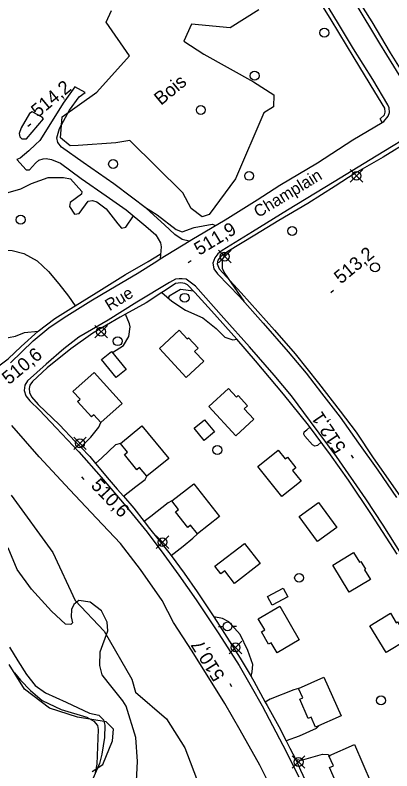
# Model space of a CAD drawing. Extents: x 347059 to 352153, y 6073752 to 6078601.
# Drawn here: x 348714.1 to 348840.8, y 6075207.5 to 6075461.9 of the extents above; entities that cross this region are included whole.
import ezdxf

# ---------------------------------------------------------------- set-up
doc = ezdxf.new("R2010")
doc.units = 0
for name, color, linetype in [('Level 1', 7, 'Continuous'), ('Level 19', 7, 'Continuous'), ('Level 2', 7, 'Continuous'), ('Level 21', 7, 'Continuous'), ('Level 22', 7, 'Continuous'), ('Level 3', 7, 'Continuous'), ('Level 31', 7, 'Continuous'), ('Level 36', 7, 'Continuous'), ('Level 4', 7, 'Continuous'), ('Level 44', 7, 'Continuous')]:
    doc.layers.add(name, color=color, linetype=linetype)

msp = doc.modelspace()

# ---------------------------------------------------------------- linework, layer by layer
at = {"layer": 'Level 1'}
msp.add_lwpolyline([(348754.72, 6075199.82), (348755.28, 6075210.65), (348754.72, 6075218.69), (348751.45, 6075229.25), (348750.34, 6075231.12), (348745.39, 6075237.26), (348743.4, 6075239.84), (348742.57, 6075242.92), (348742.68, 6075247.6), (348745.31, 6075254.6), (348745.04, 6075257.55), (348743.18, 6075261.42), (348739.33, 6075264.33), (348735.5, 6075264.86), (348733.89, 6075263.52), (348733.03, 6075261.83), (348732.92, 6075259.33), (348733.4, 6075257.32), (348732.85, 6075256.79), (348731.05, 6075256.88), (348726.3, 6075261.31), (348719.57, 6075268.69), (348714.74, 6075275.31), (348711.69, 6075282.58)], dxfattribs=at)
at = {"layer": 'Level 19'}
for points in [[(348772.58, 6075385.79), (348770.33, 6075386.41), (348767.77, 6075388.04), (348764.32, 6075391.28), (348758.33, 6075396.76), (348753.26, 6075400.67), (348747.29, 6075405.12), (348736.94, 6075412.32), (348729.69, 6075417.5), (348728.43, 6075419.01), (348728.13, 6075420.64), (348728.99, 6075423.76), (348732.4, 6075429.89), (348735.61, 6075434.35), (348737.68, 6075435.84), (348734.12, 6075437.77), (348730.24, 6075432.3), (348723.71, 6075421.79), (348722.41, 6075419.73), (348720.96, 6075418.31), (348718.68, 6075416.26), (348715.81, 6075413.74), (348714.61, 6075413.27), (348717.83, 6075409.78), (348718.97, 6075409.8), (348720.91, 6075412.08), (348722.03, 6075413.08), (348723.51, 6075413.56), (348724.55, 6075413.67), (348726.32, 6075413.26), (348729.38, 6075412.04), (348736.35, 6075406.92), (348744.73, 6075401.1), (348751.42, 6075396.41), (348758.11, 6075390.91), (348761.37, 6075387.9), (348763.02, 6075385.28), (348763.26, 6075383.9), (348762.93, 6075379.82)], [(348708.62, 6075382.07), (348710.74, 6075382.77), (348713.04, 6075382.72), (348717.06, 6075381.7), (348721.52, 6075379.23), (348725.3, 6075375.59), (348728.78, 6075371.41), (348732.03, 6075367.33), (348734.32, 6075364.05)], [(348763.41, 6075368.49), (348766.82, 6075365.67), (348771.39, 6075362.62), (348777.2, 6075359.99), (348781.68, 6075356.41), (348784.67, 6075353.54), (348787.3, 6075352.64), (348788.63, 6075352.77)], [(348746.8, 6075348.29), (348750.56, 6075350.66), (348752.32, 6075353.7), (348752.75, 6075356.98), (348752.55, 6075357.95), (348751.2, 6075361.22)], [(348701.43, 6075348.24), (348702.24, 6075350.79), (348702.71, 6075351.41), (348707.09, 6075352.48), (348714.22, 6075353.87), (348717.26, 6075355.11), (348721.81, 6075355.53)], [(348736.14, 6075316.5), (348739.54, 6075319.84), (348742.28, 6075323.17), (348742.95, 6075324.72)], [(348817.04, 6075318.13), (348815.85, 6075317.07), (348814.92, 6075316.79), (348814.15, 6075317.21), (348811.51, 6075320.17), (348811.16, 6075320.86), (348811.37, 6075321.64), (348812.24, 6075322.36), (348813.27, 6075323.17)], [(348749.48, 6075317.76), (348747.83, 6075317.29), (348743.25, 6075312.83), (348741.14, 6075311.01)], [(348750.52, 6075299.96), (348754.69, 6075303.19), (348757.8, 6075305.61), (348758.43, 6075306.66)], [(348766.76, 6075298.36), (348765.58, 6075297.69), (348759.69, 6075293.18), (348757.46, 6075291.49)], [(348766.55, 6075279.95), (348770.56, 6075283.19), (348773.81, 6075285.81), (348775.38, 6075287.28)], [(348793.5, 6075239.24), (348793.86, 6075240.81), (348794.01, 6075243.34), (348792.38, 6075248.02), (348789.79, 6075253.4), (348785.94, 6075257.67), (348783.9, 6075258.85), (348780.88, 6075259.37)], [(348809.38, 6075235.28), (348807.81, 6075234.73), (348799.85, 6075231.6), (348798.23, 6075230.63)], [(348816.3, 6075222.71), (348815.31, 6075221.82), (348809.62, 6075219.14), (348805.21, 6075217.64)], [(348808.47, 6075211.37), (348809.48, 6075211.23), (348810.42, 6075211.1), (348817.49, 6075213.11), (348819.45, 6075212.96), (348819.83, 6075212.21)]]:
    msp.add_lwpolyline(points, dxfattribs=at)
at = {"layer": 'Level 2'}
for points in [[(348717.87, 6075420.27), (348723.59, 6075427.03), (348723.15, 6075427.57), (348719.83, 6075429.39), (348718.91, 6075428.78), (348716.12, 6075423.99), (348715.49, 6075422.05), (348715.64, 6075420.97), (348716.35, 6075420.29), (348717.87, 6075420.27)], [(348710.94, 6075401.94), (348716.01, 6075403.44), (348719.64, 6075405.24), (348725.17, 6075407.28), (348730.31, 6075407.25), (348732.69, 6075406.75), (348736.54, 6075402.49), (348736.45, 6075401.6), (348732.58, 6075398.83), (348732.37, 6075397.54), (348734.06, 6075394.88), (348735.6, 6075395.11), (348738.71, 6075399.33), (348740.13, 6075399.53), (348741.6, 6075399.03), (348744.68, 6075396.69), (348748.61, 6075391.61), (348749.88, 6075390.17), (348751.35, 6075390.49), (348753.9, 6075394.37)], [(348757.56, 6075397.35), (348761.9, 6075394.65), (348768.23, 6075389.75), (348770.26, 6075388.95), (348774.34, 6075390.37), (348780.42, 6075391.5), (348781.65, 6075391.14)], [(348784.83, 6075381.76), (348783.78, 6075379.4), (348783.74, 6075376.74), (348784.57, 6075375.02), (348790.98, 6075365.59), (348791.12, 6075365.41)], [(348774.13, 6075368.93), (348769.69, 6075369.54), (348765.9, 6075367.3), (348765.52, 6075366.75)], [(348712.21, 6075249.2), (348715.04, 6075244.5), (348717.96, 6075240), (348720.8, 6075236.25), (348724.34, 6075233.73), (348731.3, 6075230.61), (348739.08, 6075226.97), (348742.2, 6075226.24), (348743.79, 6075224.64), (348744.28, 6075222.92), (348744.12, 6075218.79), (348743.24, 6075213.13), (348742.52, 6075209.99), (348739.58, 6075203.29)]]:
    msp.add_lwpolyline(points, dxfattribs=at)
at = {"layer": 'Level 21'}
for points in [[(348839.48, 6075431.73), (348834.39, 6075440.28), (348827.93, 6075450.56), (348822.91, 6075458.94), (348815.03, 6075472.01)], [(348901.69, 6075464.54), (348887.33, 6075455.72), (348875.86, 6075448.78), (348865.46, 6075442.27), (348856.18, 6075436.68), (348852.01, 6075434.36), (348850.3, 6075434.07), (348848.99, 6075434.19), (348847.94, 6075434.82), (348846.81, 6075435.99), (348841.45, 6075444.69), (348836.72, 6075452.34), (348828.46, 6075466.15)], [(348712.56, 6075344.82), (348720.13, 6075352.3), (348725.4, 6075356.66), (348730.54, 6075360.09), (348739.58, 6075365.7), (348746.12, 6075369.62), (348755.1, 6075374.95), (348761.74, 6075379.1), (348762.93, 6075379.82), (348772.58, 6075385.79), (348773.54, 6075386.38), (348784.72, 6075392.94), (348795.48, 6075399.75), (348803.18, 6075404.62), (348815.77, 6075412.2), (348827.68, 6075419.88), (348837.61, 6075425.75), (348838.13, 6075426.06), (348839.62, 6075427.89), (348839.98, 6075429.17), (348839.87, 6075430.65), (348839.48, 6075431.73)], [(348849.58, 6075422.98), (348835.5, 6075414.47), (348821.44, 6075405.76), (348805.74, 6075396.21), (348793.92, 6075388.97), (348783.74, 6075382.65), (348782.28, 6075381.59), (348781.25, 6075380.21), (348780.63, 6075378.42), (348780.91, 6075376.54), (348782.19, 6075374.82), (348789.51, 6075367.2), (348797.57, 6075358.24), (348805.98, 6075348.59), (348811.94, 6075341.35), (348817.17, 6075334.7), (348823.39, 6075326.6), (348829.61, 6075317.77), (348836.11, 6075308.78), (348842.38, 6075299.53)], [(348844.18, 6075280.23), (348837.85, 6075290.19), (348832.08, 6075299.11), (348822.16, 6075313.38), (348813.49, 6075325.16), (348807.08, 6075333.76), (348801.26, 6075340.67), (348792.88, 6075350.19), (348784.3, 6075359.86), (348774.77, 6075370.68), (348771.61, 6075373.03), (348770.27, 6075373.19), (348769.23, 6075373.16), (348768.07, 6075373.03), (348766.07, 6075371.9), (348755.08, 6075365.27), (348745.34, 6075359.24), (348735.54, 6075353.45), (348730.44, 6075349.52), (348724.48, 6075344.36), (348718.28, 6075338.77), (348717.4, 6075337.38), (348717.11, 6075335.55), (348717.64, 6075333.74), (348719.01, 6075332.09), (348722.26, 6075328.91), (348727.85, 6075323), (348735.54, 6075314.85), (348743.07, 6075306.34), (348751.43, 6075296.47), (348758.45, 6075287.84), (348764.15, 6075280.36), (348769.11, 6075273.4), (348775.02, 6075265.12), (348782.65, 6075253.59), (348789.45, 6075242.95), (348793.46, 6075235.87), (348797.14, 6075229.36), (348800.69, 6075222.73), (348804.17, 6075216.19), (348809.53, 6075205.49)], [(348801.48, 6075199.35), (348796.39, 6075209.38), (348789.81, 6075221.19), (348784.58, 6075230.2), (348773.6, 6075247.85), (348767.32, 6075257.49), (348763.59, 6075264.87), (348756.23, 6075275.26), (348749.54, 6075284.03), (348741.47, 6075292.55), (348732.44, 6075302.15), (348722.14, 6075313.27), (348712.94, 6075323.79)]]:
    msp.add_lwpolyline(points, dxfattribs=at)
at = {"layer": 'Level 22'}
for points in [[(348837.61, 6075425.75), (348836.85, 6075426.95), (348838.29, 6075428.37), (348838.53, 6075429.25), (348838.45, 6075430.53), (348835.14, 6075436.13), (348828.18, 6075447.56), (348820.39, 6075460.34), (348812.99, 6075472.38), (348805.23, 6075485.39), (348799.62, 6075494.11), (348792.63, 6075506.03), (348786.31, 6075516.42), (348780.25, 6075526.49), (348773.72, 6075536.76), (348766.95, 6075547.96), (348764.72, 6075551), (348763.64, 6075551.84), (348762.61, 6075552.18), (348761.64, 6075552.35), (348760.24, 6075551.94), (348756.72, 6075549.93), (348749.31, 6075544.99), (348744.96, 6075541.98)], [(348901.69, 6075464.54), (348900.87, 6075465.84), (348895.33, 6075462.45), (348884.32, 6075455.81), (348874.88, 6075449.87), (348864.55, 6075443.73), (348853.03, 6075436.67), (348850.81, 6075435.72), (348850.11, 6075435.75), (348849.01, 6075436.26), (348848.15, 6075437.2), (348847.06, 6075438.41), (348840.37, 6075449.16), (348834.18, 6075459.65), (348826.97, 6075471.1), (348820.1, 6075482.15), (348819.03, 6075481.41)], [(348846.99, 6075419.72), (348837.89, 6075414.14), (348828.45, 6075408.65), (348821.72, 6075404.35), (348812.53, 6075398.47), (348802.79, 6075392.8), (348794.71, 6075387.84), (348785.6, 6075382.32), (348783.12, 6075380.5), (348782.24, 6075379.39), (348782.08, 6075378.13), (348782.71, 6075376.47), (348790.16, 6075368.43), (348801.3, 6075355.86), (348808.26, 6075347.87), (348816.19, 6075337.97), (348823.44, 6075328.63), (348828.79, 6075321.48), (348834.51, 6075312.9), (348838, 6075307.97), (348844.48, 6075298.66)], [(348707.59, 6075343.19), (348711.76, 6075346.2), (348716.1, 6075350.35), (348721.81, 6075355.53), (348727.43, 6075359.74), (348733.77, 6075363.71), (348734.32, 6075364.05), (348741.33, 6075368.39), (348751.25, 6075374.58), (348758.79, 6075379.02), (348762.93, 6075381.47)], [(348842.61, 6075280.47), (348833.95, 6075293.77), (348826.21, 6075305.33), (348820.21, 6075313.9), (348812.77, 6075323.84), (348804.35, 6075334.31), (348794.9, 6075345.58), (348788.63, 6075352.77), (348780.15, 6075362.39), (348774.51, 6075368.54), (348772.11, 6075371.06), (348771.16, 6075371.56), (348769.87, 6075371.84), (348768.03, 6075371.52), (348764.53, 6075369.21), (348763.41, 6075368.49), (348758.17, 6075365.08), (348751.2, 6075361.22), (348749.4, 6075360.22), (348740.18, 6075354.84), (348732.77, 6075349.61), (348724.88, 6075343.15), (348719.88, 6075338.56), (348719.03, 6075337.32), (348718.84, 6075336.19), (348718.96, 6075334.86), (348719.57, 6075333.41), (348721.8, 6075330.82), (348728.96, 6075324.03), (348734.32, 6075318.39), (348736.14, 6075316.5), (348739.24, 6075313.29), (348741.14, 6075311.01), (348745.77, 6075305.45), (348748.44, 6075302.32), (348750.52, 6075299.96), (348754.03, 6075295.96), (348757.46, 6075291.49), (348759.33, 6075289.05), (348765.35, 6075281.54), (348766.55, 6075279.95), (348770.99, 6075274.03), (348775.32, 6075267.74), (348779.33, 6075261.73), (348780.88, 6075259.37), (348784.57, 6075253.72), (348789.82, 6075245.41), (348793.5, 6075239.24), (348794.42, 6075237.7), (348798.23, 6075230.63), (348798.85, 6075229.47), (348802.78, 6075222.48), (348805.21, 6075217.64), (348806.44, 6075215.18), (348808.47, 6075211.37), (348810.11, 6075207.77)], [(348810.11, 6075207.77), (348814.85, 6075197.45)]]:
    msp.add_lwpolyline(points, dxfattribs=at)
at = {"layer": 'Level 3'}
for p, q in [((348718.4, 6075424.57), (348719.32, 6075425.34)), ((348772.29, 6075378.65), (348773.32, 6075379.27)), ((348820.32, 6075368.5), (348821.24, 6075369.27)), ((348827.96, 6075312.74), (348827.29, 6075313.73)), ((348736.39, 6075306.47), (348737.22, 6075305.61)), ((348787.03, 6075235.81), (348786.4, 6075236.82))]:
    msp.add_line(p, q, dxfattribs=at)
at = {"layer": 'Level 31'}
for points in [[(348771.6, 6075339.92), (348762.62, 6075349.71), (348769.3, 6075355.83), (348771.98, 6075352.9), (348772.45, 6075353.33), (348775.67, 6075349.81), (348774.48, 6075348.73), (348777.55, 6075345.38), (348771.6, 6075339.92)], [(348746.45, 6075348.72), (348751.43, 6075342.65), (348748.07, 6075339.9), (348743.09, 6075345.97), (348746.45, 6075348.72)], [(348740.64, 6075341.64), (348750.1, 6075331.18), (348742.95, 6075324.72), (348740.54, 6075327.38), (348739.74, 6075326.66), (348735.06, 6075331.84), (348735.92, 6075332.62), (348733.55, 6075335.23), (348740.64, 6075341.64)], [(348788.28, 6075320.32), (348779.27, 6075330.16), (348785.86, 6075336.2), (348788.5, 6075333.32), (348789.06, 6075333.82), (348792.25, 6075330.34), (348791.14, 6075329.33), (348794.33, 6075325.86), (348788.28, 6075320.32)], [(348777.63, 6075318.74), (348774.28, 6075322.86), (348777.78, 6075325.71), (348781.13, 6075321.59), (348777.63, 6075318.74)], [(348756.73, 6075323.7), (348765.77, 6075312.66), (348758.43, 6075306.66), (348755.98, 6075309.65), (348755.02, 6075308.87), (348750.85, 6075313.97), (348751.89, 6075314.81), (348749.48, 6075317.76), (348756.73, 6075323.7)], [(348803.82, 6075299.84), (348795.74, 6075310.01), (348802.61, 6075315.47), (348804.98, 6075312.49), (348805.72, 6075313.08), (348808.56, 6075309.51), (348807.4, 6075308.59), (348810.28, 6075304.97), (348803.82, 6075299.84)], [(348774.17, 6075304.18), (348782.84, 6075293.13), (348775.38, 6075287.28), (348773.11, 6075290.18), (348772.17, 6075289.43), (348768.01, 6075294.74), (348768.99, 6075295.51), (348766.76, 6075298.36), (348774.17, 6075304.18)], [(348816.18, 6075297.88), (348822.34, 6075289.48), (348815.85, 6075284.72), (348809.69, 6075293.12), (348816.18, 6075297.88)], [(348791.24, 6075284.04), (348796.48, 6075277.28), (348787.9, 6075270.62), (348784.59, 6075274.88), (348783.31, 6075273.88), (348781.32, 6075276.43), (348791.19, 6075284.09), (348791.24, 6075284.04)], [(348826.48, 6075267.64), (348820.91, 6075276.76), (348827.9, 6075281.01), (348829.89, 6075277.74), (348830.38, 6075278.03), (348831.99, 6075275.39), (348831.63, 6075275.18), (348833.58, 6075271.97), (348826.48, 6075267.64)], [(348800.52, 6075263.3), (348798.99, 6075266.23), (348804.27, 6075269), (348805.81, 6075266.07), (348800.52, 6075263.3)], [(348803.09, 6075262.9), (348809.68, 6075251.63), (348802.18, 6075247.24), (348800.2, 6075250.6), (348799.35, 6075250.1), (348796.91, 6075254.27), (348798.06, 6075254.95), (348795.88, 6075258.68), (348803.09, 6075262.9)], [(348838.89, 6075247.31), (348833.4, 6075256.34), (348840.32, 6075260.55), (348842.27, 6075257.35), (348842.74, 6075257.64), (348844.38, 6075254.93), (348844.03, 6075254.72), (348845.93, 6075251.59), (348838.89, 6075247.31)], [(348817.93, 6075239.09), (348823.75, 6075226.04), (348815.13, 6075222.19), (348813.63, 6075225.57), (348812.68, 6075225.15), (348809.82, 6075231.59), (348810.83, 6075232.04), (348809.38, 6075235.28), (348817.93, 6075239.09)], [(348828.2, 6075216.35), (348833.87, 6075203.4), (348825.26, 6075199.64), (348823.88, 6075202.8), (348822.64, 6075202.26), (348819.85, 6075208.62), (348821.15, 6075209.19), (348819.65, 6075212.62), (348828.2, 6075216.35)]]:
    msp.add_lwpolyline(points, dxfattribs=at)
at = {"layer": 'Level 36'}
for p, q in [((348831.03, 6075405.69), (348826.8, 6075409.92)), ((348826.8, 6075405.69), (348831.03, 6075409.92)), ((348786.72, 6075378.51), (348782.49, 6075382.74)), ((348782.49, 6075378.51), (348786.72, 6075382.74)), ((348745.12, 6075353.22), (348740.89, 6075357.45)), ((348740.89, 6075353.22), (348745.12, 6075357.45)), ((348738.01, 6075315.66), (348733.78, 6075319.89)), ((348733.78, 6075315.66), (348738.01, 6075319.89)), ((348765.77, 6075282.37), (348761.54, 6075286.6)), ((348761.54, 6075282.37), (348765.77, 6075286.6)), ((348782.55, 6075256.12), (348784.05, 6075256.12)), ((348788.55, 6075256.12), (348787.05, 6075256.12)), ((348790.34, 6075246.94), (348786.11, 6075251.17)), ((348786.11, 6075246.94), (348790.34, 6075251.17)), ((348811.55, 6075208.38), (348807.32, 6075212.61)), ((348807.32, 6075208.38), (348811.55, 6075212.61))]:
    msp.add_line(p, q, dxfattribs=at)
for centre in [(348818.09, 6075456), (348794.64, 6075441.52), (348776.55, 6075429.98), (348747.05, 6075411.79), (348792.81, 6075407.8), (348828.92, 6075407.81), (348715.95, 6075393.03), (348807.28, 6075389.25), (348784.61, 6075380.63), (348835.18, 6075376.99), (348771.12, 6075366.75), (348743.01, 6075355.34), (348748.6, 6075352.14), (348735.9, 6075317.78), (348782.1, 6075315.51), (348763.66, 6075284.49), (348809.62, 6075272.48), (348785.54, 6075256.12), (348788.23, 6075249.06), (348837.17, 6075231.22), (348809.44, 6075210.5)]:
    msp.add_circle(centre, 1.5, dxfattribs=at)
at = {"layer": 'Level 4'}
for points in [[(348713.84, 6075240.56), (348715.84, 6075238.06), (348719.24, 6075234.61), (348723.18, 6075231.24), (348729.62, 6075228.12), (348738.23, 6075225.58), (348740.59, 6075224.29)], [(348740.59, 6075224.29), (348741.81, 6075222.73), (348742.06, 6075221.43), (348741.59, 6075209.72), (348740.99, 6075206.81)]]:
    msp.add_lwpolyline(points, dxfattribs=at)
at = {"layer": 'Level 44'}
for points in [[(348773.33, 6075396.84), (348770.45, 6075402.11), (348752.68, 6075419.66), (348748.01, 6075418.95), (348735.26, 6075417.99), (348732.62, 6075417.91), (348729.34, 6075420.59), (348729.92, 6075427.67), (348741.62, 6075436.02), (348752.53, 6075448.21), (348744.72, 6075459.58), (348746.47, 6075463.44)], [(348796.08, 6075463.71), (348786.39, 6075457.63), (348773.42, 6075458.88), (348770.84, 6075453.16), (348777.51, 6075448.77), (348794.32, 6075439.43), (348801.15, 6075435.03), (348801.03, 6075431.02), (348797.72, 6075429.03), (348788.25, 6075406.78), (348779.41, 6075394.8), (348777.03, 6075394.03), (348773.33, 6075396.84)], [(348712.74, 6075300.28), (348726.77, 6075281.04), (348734.33, 6075264.87), (348744, 6075254.51), (348753.31, 6075238.42), (348754.55, 6075234.03), (348765.01, 6075225.07), (348771.19, 6075215.28), (348776.03, 6075202.56), (348779.87, 6075188.87), (348780.77, 6075170.93), (348790.88, 6075158.94), (348792.76, 6075153.41), (348790.59, 6075148.76), (348793.16, 6075143.49), (348809.13, 6075137.71), (348812.19, 6075133.3), (348819.41, 6075118.62), (348826.53, 6075104.61), (348827.71, 6075096.84), (348826.63, 6075089.61), (348827.89, 6075074.66), (348821.42, 6075066.29)], [(348739.97, 6075207.29), (348743.58, 6075209.67), (348746.86, 6075217.67), (348747.16, 6075221.53), (348744.66, 6075223.99), (348735.06, 6075225.55), (348725.6, 6075228.58), (348717.2, 6075235.04), (348712.12, 6075243.35)]]:
    msp.add_lwpolyline(points, dxfattribs=at)

# ---------------------------------------------------------------- texts
at = {"layer": 'Level 21'}
for s, p in [('Champlain', (348795.89, 6075393.59)), ('Rue', (348745.86, 6075362.19))]:
    msp.add_text(s, height=4, rotation=31.4079, dxfattribs=at).set_placement(p)
at = {"layer": 'Level 3'}
for s, rotation, p in [('514,2', 39.62, (348721.76, 6075427.28)), ('511,9', 31.1799, (348776.02, 6075380.85)), ('513,2', 39.62, (348823.68, 6075371.22)), ('510,6', 39.62, (348711.98, 6075337.3)), ('512,1', 123.9103, (348825.6, 6075316.36)), ('510,6', 313.6731, (348739.33, 6075303.32)), ('510,7', 122.0643, (348784.79, 6075239.5))]:
    msp.add_text(s, height=4.5, rotation=rotation, dxfattribs=at).set_placement(p)
at = {"layer": 'Level 44'}
msp.add_text('Bois', height=4.5, rotation=39.568, dxfattribs=at).set_placement((348763.14, 6075431.34))

doc.saveas('drawing.dxf')
